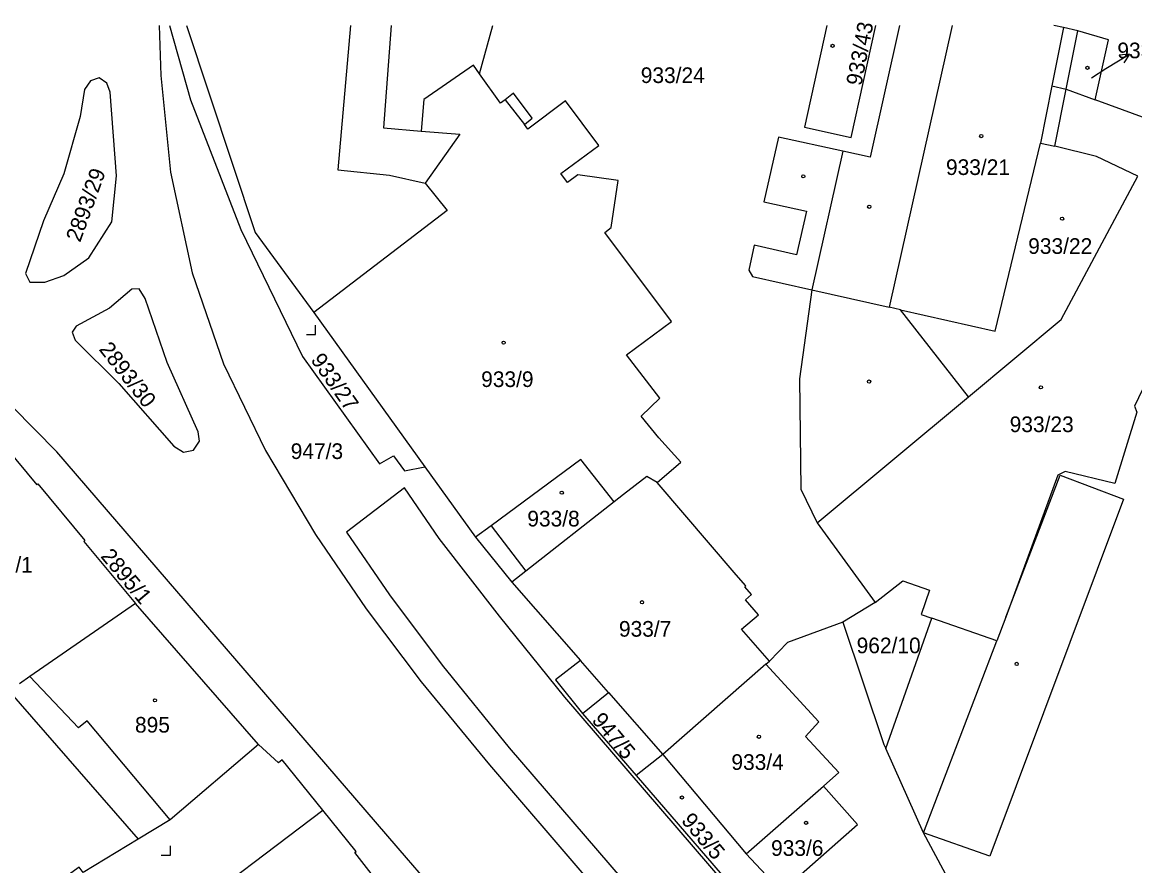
# Model space of a CAD drawing. Extents: x -496682 to -495907, y -1088575 to -1088018.
# Drawn here: x -496196 to -496075.2, y -1088110.8 to -1088019.1 of the extents above; entities that cross this region are included whole.
import ezdxf

# ---------------------------------------------------------------- set-up
doc = ezdxf.new("R2010")
doc.units = 0
for name, color, linetype in [('Hranice parcel', 7, 'Continuous'), ('Parcelní čísla', 7, 'Continuous'), ('Pop  PČ popisy', 7, 'Continuous'), ('Vnitřní kresba', 7, 'Continuous'), ('Značky budov', 7, 'Continuous'), ('Značky kultur', 7, 'Continuous')]:
    doc.layers.add(name, color=color, linetype=linetype)

msp = doc.modelspace()

# ---------------------------------------------------------------- linework, layer by layer
at = {"layer": 'Hranice parcel'}
for p, q in [((-496178.18, -1088019.49), (-496170.73, -1088041.99)), ((-496082.65, -1088026.4), (-496081.38, -1088020.07)), ((-496083.9, -1088032.61), (-496082.65, -1088026.4)), ((-496082.65, -1088026.4), (-496079.51, -1088027.56)), ((-496072.31, -1088030.21), (-496079.51, -1088027.56)), ((-496170.73, -1088041.99), (-496164.34, -1088050.67)), ((-496164.34, -1088050.67), (-496152.29, -1088067.45)), ((-496109.71, -1088073.53), (-496093.28, -1088059.84)), ((-496154.5, -1088067.86), (-496152.29, -1088067.45)), ((-496152.29, -1088067.45), (-496146.81, -1088075.09)), ((-496109.71, -1088073.53), (-496103.4, -1088082.18)), ((-496146.81, -1088075.09), (-496142.85, -1088079.96)), ((-496170.34, -1088097.61), (-496183.71, -1088082.3)), ((-496103.4, -1088082.18), (-496106.9, -1088084.33)), ((-496102.25, -1088098.03), (-496097.26, -1088083.87)), ((-496114.88, -1088088.54), (-496117.9, -1088085.09)), ((-496115.26, -1088088.87), (-496126.45, -1088098.68)), ((-496115.26, -1088088.87), (-496114.88, -1088088.54)), ((-496197.46, -1088091.77), (-496183.44, -1088107.88)), ((-496135.16, -1088094.24), (-496129.35, -1088100.96)), ((-496126.45, -1088098.68), (-496129.35, -1088100.96)), ((-496126.45, -1088098.68), (-496117.39, -1088109.46)), ((-496117.39, -1088109.46), (-496108.99, -1088102.12)), ((-496113.57, -1088113.57), (-496117.39, -1088109.46))]:
    msp.add_line(p, q, dxfattribs=at)
for points in [[(-496121.59, -1088147.94), (-496135.68, -1088131.58), (-496139.54, -1088127.1), (-496152.9, -1088111.52), (-496154.28, -1088109.93), (-496192.25, -1088065.81), (-496197.08, -1088060.92), (-496210.28, -1088048.82), (-496224.09, -1088036.2), (-496238.46, -1088023.17), (-496242.49, -1088019.49)], [(-496181.15, -1088019.49), (-496180.97, -1088024.95), (-496179.9, -1088035.45), (-496177.55, -1088046.36), (-496174.16, -1088056.24), (-496169.6, -1088065.68), (-496164.16, -1088074.78), (-496158.66, -1088082.86), (-496152.68, -1088090.79), (-496145.28, -1088099.81), (-496124.8, -1088123.7), (-496085.88, -1088168.81)], [(-496180.03, -1088019.49), (-496177.74, -1088027.59), (-496172.28, -1088041.67), (-496165.58, -1088055.45), (-496157.22, -1088067.11), (-496155.69, -1088066.25), (-496154.5, -1088067.86)], [(-496146.36, -1088024.77), (-496144.91, -1088019.49)], [(-496100.76, -1088019.49), (-496103.94, -1088033.79), (-496106.92, -1088033.15), (-496113.91, -1088031.64), (-496115.49, -1088038.67), (-496110.87, -1088039.68), (-496111.93, -1088044.4), (-496116.54, -1088043.38), (-496117.12, -1088046.07), (-496116.72, -1088046.75), (-496110.28, -1088048.21), (-496111.6, -1088057.9), (-496111.47, -1088069.87), (-496109.71, -1088073.53)], [(-496108.63, -1088019.49), (-496111.06, -1088030.56), (-496105.99, -1088031.67), (-496103.31, -1088019.49)], [(-496081.38, -1088020.07), (-496082.94, -1088019.72), (-496083.98, -1088019.49)], [(-496079.51, -1088027.56), (-496078.06, -1088021.06), (-496081.38, -1088020.07)], [(-496146.36, -1088024.77), (-496147.01, -1088023.8), (-496152.39, -1088027.53), (-496152.68, -1088030.97), (-496148.5, -1088031.32), (-496152.25, -1088036.62)], [(-496189.72, -1088029.38), (-496191.51, -1088035.6), (-496193.69, -1088040.71), (-496195.65, -1088046.45), (-496195.19, -1088047.37), (-496193.56, -1088047.37), (-496191.5, -1088046.66), (-496188.77, -1088044.74), (-496186.3, -1088040.83), (-496185.78, -1088035.84), (-496186.46, -1088026.73), (-496186.84, -1088025.75), (-496187.65, -1088025.2), (-496188.59, -1088025.53), (-496189.26, -1088026.45), (-496189.72, -1088029.38)], [(-496127.07, -1088069.16), (-496124.51, -1088066.95), (-496126.89, -1088064.3), (-496128.79, -1088061.95), (-496126.78, -1088059.98), (-496130.39, -1088055.28), (-496125.53, -1088051.64), (-496132.74, -1088041.98), (-496132.05, -1088041.46), (-496131.31, -1088036.33), (-496135.69, -1088035.73), (-496136.8, -1088036.56), (-496137.53, -1088035.58), (-496133.41, -1088032.52), (-496137.02, -1088027.69), (-496141.11, -1088030.77), (-496141.49, -1088030.26), (-496140.65, -1088029.57), (-496142.68, -1088026.85), (-496143.57, -1088027.57), (-496144.08, -1088027.93), (-496146.36, -1088024.77)], [(-496093.28, -1088059.84), (-496100.63, -1088050.4), (-496090.35, -1088052.7), (-496085.46, -1088032.3), (-496083.9, -1088032.61)], [(-496093.28, -1088059.84), (-496083.21, -1088051.44), (-496074.87, -1088035.85), (-496079.37, -1088033.74), (-496083.9, -1088032.61)], [(-496062.85, -1088035.07), (-496075.24, -1088060.86), (-496075, -1088061.51), (-496077.39, -1088069.25), (-496082.78, -1088067.93), (-496083.58, -1088068.36), (-496089.22, -1088083.77), (-496090.2, -1088086.33), (-496097.26, -1088083.87)], [(-496152.25, -1088036.62), (-496149.86, -1088039.59), (-496164.34, -1088050.67)], [(-496176.77, -1088064.66), (-496176.9, -1088063.64), (-496180.28, -1088056.11), (-496182.66, -1088049.14), (-496183.33, -1088048.12), (-496184.1, -1088048.13), (-496186.54, -1088050.2), (-496190.16, -1088052.15), (-496190.58, -1088052.82), (-496190.25, -1088053.68), (-496185.53, -1088058.39), (-496179.54, -1088065.21), (-496178.5, -1088065.84), (-496177.4, -1088065.63), (-496176.77, -1088064.66)], [(-496200.06, -1088062.62), (-496194.43, -1088069.4), (-496194.32, -1088069.3), (-496189.2, -1088075.46), (-496189.32, -1088075.56), (-496183.71, -1088082.3)], [(-496131.73, -1088071.25), (-496135.34, -1088066.64), (-496145.11, -1088073.84), (-496146.81, -1088075.09)], [(-496127.07, -1088069.16), (-496128.19, -1088068.5), (-496130.72, -1088070.46), (-496131.73, -1088071.25)], [(-496117.9, -1088085.09), (-496116.07, -1088083.5), (-496117.48, -1088081.89), (-496116.83, -1088081.32), (-496117.56, -1088080.48), (-496117.44, -1088080.37), (-496118.48, -1088079.17), (-496127.07, -1088069.16)], [(-496116.26, -1088116.72), (-496137.09, -1088092.45), (-496144.2, -1088083.68), (-496150.73, -1088075.21), (-496154.49, -1088069.71), (-496160.82, -1088074.53), (-496156.15, -1088081.34), (-496150.43, -1088088.98), (-496143.13, -1088097.97), (-496122.6, -1088121.81), (-496081, -1088170.14)], [(-496131.73, -1088071.25), (-496141.32, -1088078.77), (-496142.85, -1088079.96)], [(-496142.85, -1088079.96), (-496135.39, -1088088.47), (-496138.11, -1088090.59), (-496135.16, -1088094.24)], [(-496103.4, -1088082.18), (-496100.38, -1088079.84), (-496097.49, -1088080.85), (-496098.41, -1088083.47), (-496097.26, -1088083.87)], [(-496183.71, -1088082.3), (-496195.19, -1088090.23), (-496196.3, -1088091)], [(-496106.9, -1088084.33), (-496112.93, -1088086.52), (-496114.88, -1088088.54)], [(-496106.9, -1088084.33), (-496102.44, -1088097.6), (-496102.25, -1088098.03)], [(-496108.99, -1088102.12), (-496107.34, -1088100.65), (-496110.97, -1088096.75), (-496109.53, -1088095.14), (-496115.26, -1088088.87)], [(-496135.16, -1088094.24), (-496132.34, -1088091.95), (-496126.45, -1088098.68)], [(-496170.34, -1088097.61), (-496179.96, -1088105.77), (-496183.44, -1088107.88)], [(-496163.37, -1088104.73), (-496167.79, -1088099.27), (-496168.2, -1088099.6), (-496170.34, -1088097.61)], [(-496063.87, -1088167.88), (-496084, -1088133.61), (-496098.14, -1088107.2), (-496102.25, -1088098.03)], [(-496129.35, -1088100.96), (-496116.34, -1088116.02), (-496113.57, -1088113.57)], [(-496113.57, -1088113.57), (-496105.32, -1088106.28), (-496108.99, -1088102.12)], [(-496191.24, -1088126.97), (-496179.64, -1088117.06), (-496163.37, -1088104.73)], [(-496157.35, -1088112.6), (-496159.89, -1088109.34), (-496159.74, -1088109.21), (-496163.37, -1088104.73)], [(-496183.44, -1088107.88), (-496189.41, -1088111.49), (-496189.82, -1088110.92), (-496195.38, -1088114.92)]]:
    msp.add_lwpolyline(points, dxfattribs=at)
at = {"layer": 'Pop  PČ popisy'}
for p, q in [((-496078.34, -1088024.19), (-496075.79, -1088022.6)), ((-496075.79, -1088022.6), (-496076.91, -1088022.71)), ((-496075.79, -1088022.6), (-496076.38, -1088023.55)), ((-496079.92, -1088025.18), (-496078.34, -1088024.19))]:
    msp.add_line(p, q, dxfattribs=at)
at = {"layer": 'Vnitřní kresba'}
for p, q in [((-496160.36, -1088019.49), (-496161.76, -1088035.17)), ((-496155.95, -1088019.49), (-496156.79, -1088030.63)), ((-496095.02, -1088019.49), (-496101.89, -1088050.11)), ((-496082.94, -1088019.72), (-496084.21, -1088026.05)), ((-496084.21, -1088026.05), (-496085.46, -1088032.3)), ((-496084.21, -1088026.05), (-496082.65, -1088026.4)), ((-496143.57, -1088027.57), (-496141.49, -1088030.26)), ((-496156.79, -1088030.63), (-496152.68, -1088030.97)), ((-496106.92, -1088033.15), (-496110.28, -1088048.21)), ((-496161.76, -1088035.17), (-496156.14, -1088035.76)), ((-496156.14, -1088035.76), (-496152.25, -1088036.62)), ((-496110.28, -1088048.21), (-496101.89, -1088050.11)), ((-496100.63, -1088050.4), (-496101.89, -1088050.11)), ((-496089.22, -1088083.77), (-496083.31, -1088068.36)), ((-496083.31, -1088068.36), (-496076.43, -1088070.94)), ((-496076.43, -1088070.94), (-496090.95, -1088109.74)), ((-496145.11, -1088073.84), (-496141.32, -1088078.77)), ((-496098.14, -1088107.2), (-496090.2, -1088086.33)), ((-496132.34, -1088091.95), (-496135.39, -1088088.47)), ((-496189.91, -1088095.8), (-496195.19, -1088090.23)), ((-496188.97, -1088095.02), (-496189.91, -1088095.8)), ((-496179.96, -1088105.77), (-496188.97, -1088095.02)), ((-496090.95, -1088109.74), (-496098.14, -1088107.2))]:
    msp.add_line(p, q, dxfattribs=at)
at = {"layer": 'Značky budov'}
for centre in [(-496108.02, -1088021.71), (-496080.35, -1088024.1), (-496091.88, -1088031.52), (-496111.2, -1088035.89), (-496104.04, -1088039.19), (-496083.1, -1088040.49), (-496143.74, -1088053.95), (-496104.06, -1088058.18), (-496085.4, -1088058.81), (-496137.43, -1088070.25), (-496128.71, -1088082.15), (-496088.03, -1088088.85), (-496181.6, -1088092.8), (-496116.02, -1088096.76), (-496124.38, -1088103.36), (-496110.9, -1088106.11)]:
    msp.add_circle(centre, 0.175, dxfattribs=at)
at = {"layer": 'Značky kultur'}
for p, q in [((-496164.16, -1088053.06), (-496164.16, -1088052.06)), ((-496165.16, -1088053.06), (-496164.16, -1088053.06)), ((-496179.93, -1088109.61), (-496179.93, -1088108.61)), ((-496180.93, -1088109.61), (-496179.93, -1088109.61))]:
    msp.add_line(p, q, dxfattribs=at)

# ---------------------------------------------------------------- texts
at = {"layer": 'Parcelní čísla'}
for s, rotation, p in [('933/43', 79, (-496104.9, -1088026.12)), ('2893/29', 70, (-496189.73, -1088043.13)), ('2893/30', 308, (-496187.75, -1088054.69)), ('933/27', 305, (-496164.75, -1088055.84)), ('2895/1', 310, (-496187.58, -1088077.19)), ('947/5', 310, (-496134.25, -1088095.01)), ('933/5', 310, (-496124.53, -1088105.91))]:
    msp.add_text(s, height=1.7, rotation=rotation, dxfattribs=at).set_placement(p)
for s, p in [('933/49', (-496077.1, -1088023.06)), ('933/24', (-496128.85, -1088025.75)), ('933/21', (-496095.71, -1088035.74)), ('933/22', (-496086.78, -1088044.31)), ('933/9', (-496146.18, -1088058.77)), ('933/23', (-496088.79, -1088063.67)), ('947/3', (-496166.86, -1088066.59)), ('933/8', (-496141.17, -1088073.92)), ('902/1', (-496200.55, -1088078.93)), ('933/7', (-496131.22, -1088085.89)), ('962/10', (-496105.41, -1088087.69)), ('895', (-496183.77, -1088096.31)), ('933/4', (-496119.01, -1088100.36)), ('933/6', (-496114.7, -1088109.7))]:
    msp.add_text(s, height=1.7, dxfattribs=at).set_placement(p)

doc.saveas('drawing.dxf')
